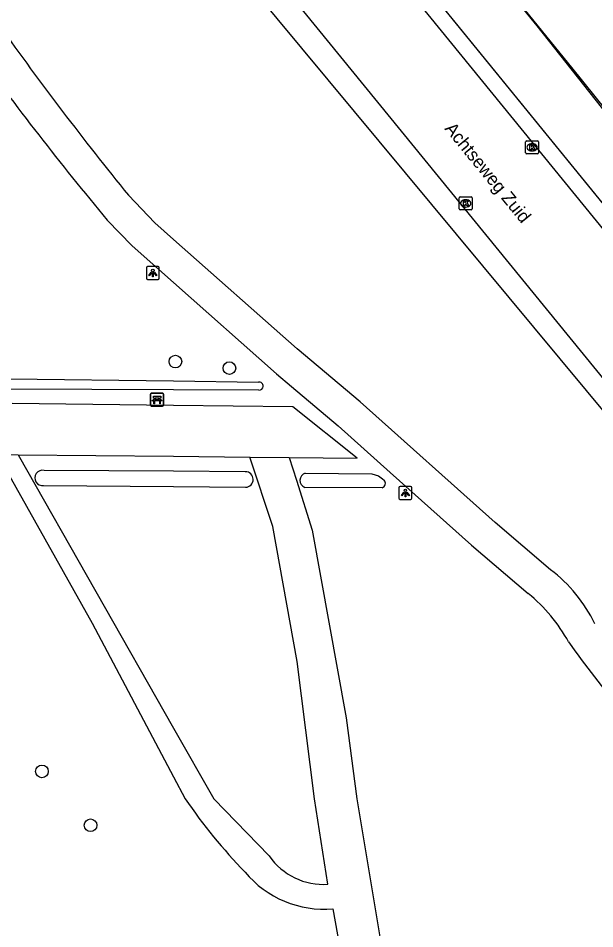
# Model space of a CAD drawing. Extents: x 157154 to 159278, y 385000 to 386650.
# Drawn here: x 158988 to 159032.6, y 385489.9 to 385560.3 of the extents above; entities that cross this region are included whole.
import ezdxf

# ---------------------------------------------------------------- set-up
doc = ezdxf.new("R2010")
doc.units = 0
for name, color, linetype in [('IMGEO_Bank', 7, 'Continuous'), ('IMGEO_Boom', 7, 'Continuous'), ('IMGEO_Fietspad_gesloten', 7, 'Continuous'), ('IMGEO_Gemengd_bos', 7, 'Continuous'), ('IMGEO_Grasland_overig', 7, 'Continuous'), ('IMGEO_Hek', 7, 'Continuous'), ('IMGEO_Kolk', 7, 'Continuous'), ('IMGEO_Lichtpunt', 7, 'Continuous'), ('IMGEO_Muur', 7, 'Continuous'), ('IMGEO_Openbare_ruimte_label', 7, 'Continuous'), ('IMGEO_Rijbaan_lokaal_open', 7, 'Continuous'), ('IMGEO_Spoorbaan_halfverhard', 7, 'Continuous'), ('IMGEO_Voetpad_halfverhard', 7, 'Continuous'), ('IMGEO_Waterloop', 7, 'Continuous')]:
    doc.layers.add(name, color=color, linetype=linetype)

msp = doc.modelspace()

# ---------------------------------------------------------------- linework, layer by layer
at = {"layer": 'IMGEO_Bank'}
for p, q in [((158998.223, 385530.429), (158998.223, 385531.27)), ((158998.223, 385531.27), (158998.223, 385530.429)), ((158998.298, 385531.354), (158999.139, 385531.354)), ((158999.139, 385531.354), (158998.298, 385531.354)), ((158998.532, 385530.86), (158998.532, 385530.966)), ((158998.576, 385530.966), (158998.576, 385530.86)), ((158998.864, 385530.972), (158998.582, 385530.972)), ((158998.87, 385530.86), (158998.87, 385530.966)), ((158998.914, 385530.966), (158998.914, 385530.86)), ((158999.223, 385531.279), (158999.223, 385530.438)), ((158999.223, 385530.438), (158999.223, 385531.279)), ((158999.148, 385530.354), (158998.307, 385530.354)), ((158998.307, 385530.354), (158999.148, 385530.354)), ((158998.92, 385530.752), (158998.527, 385530.752)), ((158998.582, 385530.854), (158998.864, 385530.854))]:
    msp.add_line(p, q, dxfattribs=at)
for points in [[(158998.526, 385530.972), (158998.44, 385530.972), (158998.44, 385531.133), (158999.003, 385531.133), (158999.003, 385530.972), (158998.92, 385530.972)], [(158998.47, 385530.752), (158998.328, 385530.752), (158998.44, 385530.854), (158998.526, 385530.854)], [(158998.52, 385530.745), (158998.52, 385530.538), (158998.477, 385530.538), (158998.477, 385530.745)], [(158998.92, 385530.854), (158999.003, 385530.854), (158999.115, 385530.752), (158998.976, 385530.752)], [(158998.97, 385530.745), (158998.97, 385530.538), (158998.926, 385530.538), (158998.926, 385530.745)]]:
    msp.add_lwpolyline(points, dxfattribs=at)
for centre, radius, start, end in [((158998.301, 385531.276), 0.0779, 92.4484, 184.28452), ((158998.301, 385531.276), 0.0779, 92.4484, 184.28452), ((158998.525, 385530.965), 0.00671, 2.89567, 87.10433), ((158998.582, 385530.965), 0.00671, 92.89567, 177.10433), ((158998.864, 385530.965), 0.00671, 2.89567, 87.10433), ((158998.921, 385530.965), 0.00671, 92.89567, 177.10433), ((158999.145, 385531.276), 0.0779, 2.4484, 94.28452), ((158999.145, 385531.276), 0.0779, 2.4484, 94.28452), ((158998.301, 385530.432), 0.0779, 182.4484, 274.28452), ((158998.301, 385530.432), 0.0779, 182.4484, 274.28452), ((158998.47, 385530.745), 0.00671, 2.89567, 87.10433), ((158998.527, 385530.745), 0.00671, 92.89567, 177.10433), ((158998.525, 385530.861), 0.00671, 272.89567, 357.10433), ((158998.582, 385530.861), 0.00671, 182.89567, 267.10433), ((158998.864, 385530.861), 0.00671, 272.89567, 357.10433), ((158998.921, 385530.861), 0.00671, 182.89567, 267.10433), ((158998.919, 385530.745), 0.00671, 2.89567, 87.10433), ((158998.976, 385530.745), 0.00671, 92.89567, 177.10433), ((158999.145, 385530.432), 0.0779, 272.4484, 4.28452), ((158999.145, 385530.432), 0.0779, 272.4484, 4.28452)]:
    msp.add_arc(centre, radius, start, end, dxfattribs=at)
at = {"layer": 'IMGEO_Boom'}
for centre in [(159000.145, 385533.799), (159004.317, 385533.288), (158989.824, 385502.114), (158993.577, 385497.947)]:
    msp.add_circle(centre, 0.489, dxfattribs=at)
at = {"layer": 'IMGEO_Fietspad_gesloten'}
for points in [[(159029.142, 385517.709), (159024.86, 385521.359), (159014.416, 385530.685), (159009.545, 385534.784), (159000, 385543.24), (158998.547, 385544.527), (158996.509, 385546.653)], [(158994.864, 385544.734), (158996.799, 385542.746), (159000, 385539.908), (159007.959, 385532.852), (159009.112, 385531.88), (159012.731, 385528.828), (159016.755, 385525.22), (159023.033, 385519.591), (159027.421, 385515.87)]]:
    msp.add_lwpolyline(points, dxfattribs=at)
for centre, radius, start, end in [((159197.453, 385709.723), 258.786, 215.40958, 219.06009), ((159198.364, 385713.61), 264.445, 216.02464, 219.68787), ((159022.075, 385508.442), 11.654, 25.86741, 52.66812), ((159019.158, 385505.827), 13.005, 28.93379, 50.55404), ((159088.987, 385552.969), 71.307, 214.95046, 225.7317)]:
    msp.add_arc(centre, radius, start, end, dxfattribs=at)
at = {"layer": 'IMGEO_Gemengd_bos'}
for points in [[(159150.273, 385385.066), (159150.167, 385385.283), (159149.043, 385387.58), (159057.676, 385500), (159035.861, 385526.812), (159000, 385569.989), (158976.812, 385598.387), (158944.195, 385637.794), (158939.671, 385643.611)], [(158986.361, 385526.609), (158993.714, 385513.564), (159000, 385501.691), (159000.899, 385500)], [(158987.993, 385526.593), (159000, 385505.456), (159003.099, 385500), (159007.4, 385495.582)], [(159011.929, 385493.393), (159010.902, 385500), (159009.563, 385510.599), (159007.682, 385521.048), (159005.896, 385526.417)], [(159008.938, 385526.388), (159009.489, 385524.634), (159010.7, 385520.775), (159013.329, 385506.25), (159014.169, 385500), (159017.133, 385482.216)], [(159012.319, 385491.49), (159014.843, 385477.432)]]:
    msp.add_lwpolyline(points, dxfattribs=at)
for centre, radius, start, end in [((159035.505, 385523.517), 41.84, 214.19887, 224.23342), ((159011.561, 385498.411), 5.031, 214.21027, 274.19802), ((159011.651, 385499.435), 7.973, 219.81418, 274.80841)]:
    msp.add_arc(centre, radius, start, end, dxfattribs=at)
at = {"layer": 'IMGEO_Grasland_overig'}
msp.add_lwpolyline([(159011.046, 385573.162), (159044.807, 385531.748), (159070.687, 385500), (159100.286, 385463.691), (159167.2, 385381.706)], dxfattribs=at)
at = {"layer": 'IMGEO_Hek'}
msp.add_lwpolyline([(159160.922, 385396.693), (159137.128, 385425.571), (159108.876, 385459.98), (159096.003, 385475.701), (159072.576, 385504.374), (159069.092, 385508.611), (159058.304, 385522.356), (159049.446, 385533.456), (159048.76, 385532.887), (159041.105, 385542.147), (159041.869, 385542.754), (159037.056, 385548.748), (159030.78, 385556.527), (159022.964, 385566.189), (159018.242, 385572.067), (159014.652, 385576.334), (159010.945, 385573.278), (159004.672, 385581.054), (158979.577, 385611.994)], dxfattribs=at)
at = {"layer": 'IMGEO_Kolk'}
for p, q in [((159027.217, 385549.933), (159027.217, 385550.785)), ((159027.292, 385550.859), (159028.144, 385550.859)), ((159027.705, 385550.639), (159027.73, 385550.639)), ((159028.218, 385550.785), (159028.218, 385549.933)), ((159027.728, 385550.079), (159027.703, 385550.079)), ((159028.144, 385549.859), (159027.292, 385549.859)), ((159022.082, 385545.597), (159022.082, 385546.449)), ((159022.157, 385546.523), (159023.009, 385546.523)), ((159023.083, 385546.449), (159023.083, 385545.597)), ((159022.593, 385545.743), (159022.568, 385545.743)), ((159022.57, 385546.303), (159022.595, 385546.303)), ((159023.009, 385545.523), (159022.157, 385545.523))]:
    msp.add_line(p, q, dxfattribs=at)
for points in [[(159027.217, 385549.933), (159027.217, 385550.785)], [(159027.292, 385550.859), (159028.144, 385550.859)], [(159028.218, 385550.785), (159028.218, 385549.933)], [(159027.538, 385550.559), (159027.661, 385550.559), (159027.661, 385550.408), (159027.791, 385550.559), (159027.955, 385550.559), (159027.809, 385550.408), (159027.962, 385550.159), (159027.81, 385550.159), (159027.725, 385550.323), (159027.661, 385550.256), (159027.661, 385550.159), (159027.538, 385550.159), (159027.538, 385550.559)], [(159028.144, 385549.859), (159027.292, 385549.859)], [(159022.082, 385545.597), (159022.082, 385546.449)], [(159022.157, 385546.523), (159023.009, 385546.523)], [(159023.083, 385546.449), (159023.083, 385545.597)], [(159022.403, 385546.223), (159022.526, 385546.223), (159022.526, 385546.072), (159022.656, 385546.223), (159022.82, 385546.223), (159022.674, 385546.072), (159022.827, 385545.823), (159022.675, 385545.823), (159022.59, 385545.987), (159022.526, 385545.92), (159022.526, 385545.823), (159022.403, 385545.823), (159022.403, 385546.223)], [(159023.009, 385545.523), (159022.157, 385545.523)]]:
    msp.add_lwpolyline(points, dxfattribs=at)
for centre, start, end in [((159027.294, 385550.783), 91.55205, 178.44795), ((159027.294, 385550.783), 91.55205, 178.44795), ((159028.142, 385550.783), 1.55205, 88.44795), ((159028.142, 385550.783), 1.55205, 88.44795), ((159027.294, 385549.935), 181.55205, 268.44795), ((159027.294, 385549.935), 181.55205, 268.44795), ((159028.142, 385549.935), 271.55205, 358.44795), ((159028.142, 385549.935), 271.55205, 358.44795), ((159022.159, 385546.447), 91.55205, 178.44795), ((159022.159, 385546.447), 91.55205, 178.44795), ((159023.007, 385546.447), 1.55205, 88.44795), ((159023.007, 385546.447), 1.55205, 88.44795), ((159022.159, 385545.599), 181.55205, 268.44795), ((159022.159, 385545.599), 181.55205, 268.44795), ((159023.007, 385545.599), 271.55205, 358.44795), ((159023.007, 385545.599), 271.55205, 358.44795)]:
    msp.add_arc(centre, 0.0765, start, end, dxfattribs=at)
for centre, major_axis, ratio, start_param, end_param in [((159027.704, 385550.359), (-0.387, 0.002), 0.722429, 4.712389, 7.853982), ((159027.729, 385550.359), (-0.39, 0.002), 0.717154, 1.570796, 4.712389), ((159022.569, 385546.023), (-0.387, 0.002), 0.722429, 4.712389, 7.853982), ((159022.594, 385546.023), (-0.39, 0.002), 0.717154, 1.570796, 4.712389)]:
    msp.add_ellipse(centre, major_axis=major_axis, ratio=ratio, start_param=start_param, end_param=end_param, dxfattribs=at)
at = {"layer": 'IMGEO_Lichtpunt'}
for p, q in [((158997.897, 385541.041), (158997.897, 385540.234)), ((158997.897, 385541.041), (158997.897, 385540.234)), ((158998.799, 385541.136), (158997.991, 385541.136)), ((158998.799, 385541.136), (158997.991, 385541.136)), ((158998.893, 385540.234), (158998.893, 385541.041)), ((158998.893, 385540.234), (158998.893, 385541.041)), ((158997.991, 385540.14), (158998.799, 385540.14)), ((158997.991, 385540.14), (158998.799, 385540.14)), ((159017.419, 385524.047), (159017.419, 385523.24)), ((159017.419, 385524.047), (159017.419, 385523.24)), ((159018.321, 385524.142), (159017.513, 385524.142)), ((159018.321, 385524.142), (159017.513, 385524.142)), ((159018.415, 385523.24), (159018.415, 385524.047)), ((159018.415, 385523.24), (159018.415, 385524.047)), ((159017.513, 385523.146), (159018.321, 385523.146)), ((159017.513, 385523.146), (159018.321, 385523.146))]:
    msp.add_line(p, q, dxfattribs=at)
for points in [[(158998.271, 385540.705), (158998.31, 385540.677), (158998.122, 385540.415), (158998.084, 385540.442), (158998.271, 385540.705)], [(158998.373, 385540.657), (158998.42, 385540.657), (158998.42, 385540.335), (158998.373, 385540.335), (158998.373, 385540.657)], [(158998.483, 385540.677), (158998.521, 385540.704), (158998.708, 385540.442), (158998.669, 385540.414), (158998.483, 385540.677)], [(159017.793, 385523.711), (159017.832, 385523.683), (159017.644, 385523.421), (159017.606, 385523.448), (159017.793, 385523.711)], [(159017.895, 385523.663), (159017.942, 385523.663), (159017.942, 385523.341), (159017.895, 385523.341), (159017.895, 385523.663)], [(159018.005, 385523.683), (159018.043, 385523.71), (159018.23, 385523.448), (159018.191, 385523.42), (159018.005, 385523.683)]]:
    msp.add_lwpolyline(points, dxfattribs=at)
for centre in [(158998.396, 385540.839), (159017.918, 385523.845)]:
    msp.add_circle(centre, 0.0994, dxfattribs=at)
for centre, start, end in [((158997.991, 385541.041), 90, 180), ((158997.991, 385541.041), 90, 180), ((158998.799, 385541.041), 0, 90), ((158998.799, 385541.041), 0, 90), ((158997.991, 385540.234), 180, 270), ((158997.991, 385540.234), 180, 270), ((158998.799, 385540.234), 270, 0), ((158998.799, 385540.234), 270, 360), ((159017.513, 385524.047), 90, 180), ((159017.513, 385524.047), 90, 180), ((159018.321, 385524.047), 0, 90), ((159018.321, 385524.047), 0, 90), ((159017.513, 385523.24), 180, 270), ((159017.513, 385523.24), 180, 270), ((159018.321, 385523.24), 270, 0), ((159018.321, 385523.24), 270, 360)]:
    msp.add_arc(centre, 0.0946, start, end, dxfattribs=at)
at = {"layer": 'IMGEO_Muur'}
msp.add_lwpolyline([(159010.937, 385573.296), (159044.807, 385531.748), (159100.286, 385463.691), (159167.2, 385381.706), (159168.34, 385381.585), (159168.595, 385381.558), (159169.474, 385380.494), (159169.729, 385380.185), (159170.502, 385379.248), (159170.444, 385378.688), (159170.356, 385377.836), (159224.612, 385309.725), (159249.549, 385278.463)], dxfattribs=at)
at = {"layer": 'IMGEO_Rijbaan_lokaal_open'}
for points in [[(158854.381, 385763.213), (159043.862, 385530.978), (159167.844, 385378.971)], [(159153.706, 385384.827), (159038.204, 385526.376), (158938.905, 385648.068)]]:
    msp.add_lwpolyline(points, dxfattribs=at)
at = {"layer": 'IMGEO_Spoorbaan_halfverhard'}
msp.add_lwpolyline([(159014.573, 385576.309), (159028.074, 385559.753), (159041.625, 385542.602)], dxfattribs=at)
at = {"layer": 'IMGEO_Voetpad_halfverhard'}
for points in [[(159008.938, 385526.388), (159014.184, 385526.339), (159009.222, 385530.285), (159000, 385530.399), (158987.527, 385530.553)], [(158986.361, 385526.609), (158987.993, 385526.593)], [(158987.993, 385526.593), (159000, 385526.475), (159005.896, 385526.417)], [(159005.896, 385526.417), (159008.938, 385526.388)]]:
    msp.add_lwpolyline(points, dxfattribs=at)
at = {"layer": 'IMGEO_Waterloop'}
for points in [[(158987.34, 385532.457), (159000, 385532.294), (159006.552, 385532.209)], [(159006.601, 385531.578), (159000, 385531.605), (158987.361, 385531.658)], [(159005.545, 385525.28), (159000, 385525.318), (158989.993, 385525.387)], [(159010.172, 385525.171), (159015.326, 385525.122), (159015.844, 385524.964), (159016.148, 385524.719), (159016.266, 385524.624)], [(158989.954, 385524.208), (159000, 385524.128), (159005.566, 385524.084)], [(159016.127, 385524.044), (159010.154, 385524.072)]]:
    msp.add_lwpolyline(points, dxfattribs=at)
for centre, radius, start, end in [((159006.606, 385531.896), 0.318, 357.15643, 99.86393), ((159006.605, 385531.898), 0.32, 269.31177, 356.8394), ((158989.872, 385524.801), 0.598, 78.34912, 277.8617), ((159005.554, 385524.682), 0.598, 271.15061, 90.86125), ((159010.348, 385524.618), 0.58, 107.67511, 178.92412), ((159010.347, 385524.618), 0.579, 178.88169, 250.56209), ((159016.029, 385524.374), 0.344, 286.51222, 46.53368)]:
    msp.add_arc(centre, radius, start, end, dxfattribs=at)

# ---------------------------------------------------------------- texts
at = {"layer": 'IMGEO_Openbare_ruimte_label'}
msp.add_text('Achtseweg Zuid', height=1, rotation=309.24106, dxfattribs=at).set_placement((159020.908, 385551.78))

doc.saveas('drawing.dxf')
